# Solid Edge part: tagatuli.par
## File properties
Author: Türk
Template: iso part.par
Last saved by: Türk
Revision: 6
Application: Solid Edge
Accuracy: 0,990
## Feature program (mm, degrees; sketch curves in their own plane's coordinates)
base feature "unnamed BaseFeature 1"
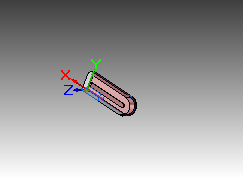
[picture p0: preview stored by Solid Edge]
